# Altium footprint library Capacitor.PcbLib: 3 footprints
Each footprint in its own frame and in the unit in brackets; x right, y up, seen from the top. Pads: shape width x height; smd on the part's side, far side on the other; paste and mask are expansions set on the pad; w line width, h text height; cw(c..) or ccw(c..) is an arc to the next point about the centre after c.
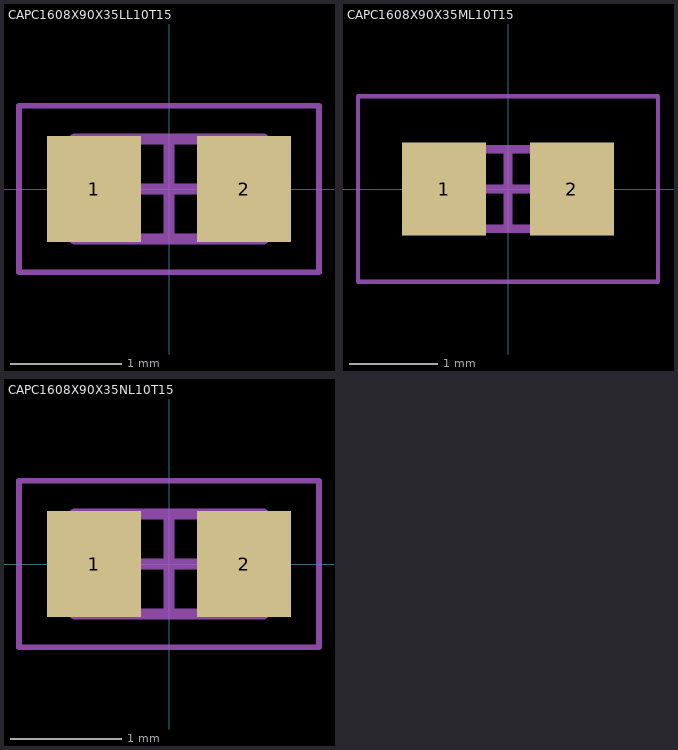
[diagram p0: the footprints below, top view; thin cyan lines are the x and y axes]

## CAPC1608X90X35LL10T15 [mm] "Chip Capacitor, 2-Leads, Body 1.60x0.80mm, IPC High Density"
height 0.9
pads (2):
  rect 0.85x0.95 smd: 1(-0.675,0) 2(0.675,0)
Mechanical 13:
  lines w0.1: -0.85,-0.45 0.85,-0.45 0.85,0.45 -0.85,0.45 -0.85,-0.45
Mechanical 15:
  lines w0.05: -1.35,-0.75 1.35,-0.75 1.35,0.75 -1.35,0.75 -1.35,-0.75
  lines w0.1: -0.45,0 0.45,0 ; 0,-0.45 0,0.45
3D body: height 0.9, standoff 0, extent 0.5,-0.45 0.85,0.45
3D body: height 0.9, standoff 0, extent -0.85,-0.45 -0.5,0.45
3D body: height 0.9, standoff 0, extent -0.5,-0.45 0.5,0.45

## CAPC1608X90X35ML10T15 [mm] "Chip Capacitor, 2-Leads, Body 1.60x0.80mm, IPC Low Density"
height 0.9
pads (2):
  rect 0.95x1.05 smd: 1(-0.725,0) 2(0.725,0)
Mechanical 13:
  lines w0.1: -0.85,-0.45 -0.85,0.45 0.85,0.45 0.85,-0.45 -0.85,-0.45
Mechanical 15:
  lines w0.05: -1.7,-1.05 -1.7,1.05 1.7,1.05 1.7,-1.05 -1.7,-1.05
  lines w0.1: -0.45,0 0.45,0 ; 0,-0.45 0,0.45
3D body: height 0.9, standoff 0, extent -0.5,-0.45 0.5,0.45
3D body: height 0.9, standoff 0, extent -0.85,-0.45 -0.5,0.45
3D body: height 0.9, standoff 0, extent 0.5,-0.45 0.85,0.45

## CAPC1608X90X35NL10T15 [mm] "Chip Capacitor, 2-Leads, Body 1.60x0.80mm, IPC Medium Density"
height 0.9
pads (2):
  rect 0.85x0.95 smd: 1(-0.675,0) 2(0.675,0)
Mechanical 13:
  lines w0.1: -0.85,-0.45 -0.85,0.45 0.85,0.45 0.85,-0.45 -0.85,-0.45
Mechanical 15:
  lines w0.05: -1.35,-0.75 -1.35,0.75 1.35,0.75 1.35,-0.75 -1.35,-0.75
  lines w0.1: -0.45,0 0.45,0 ; 0,-0.45 0,0.45
3D body: height 0.9, standoff 0, extent -0.5,-0.45 0.5,0.45
3D body: height 0.9, standoff 0, extent -0.85,-0.45 -0.5,0.45
3D body: height 0.9, standoff 0, extent 0.5,-0.45 0.85,0.45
